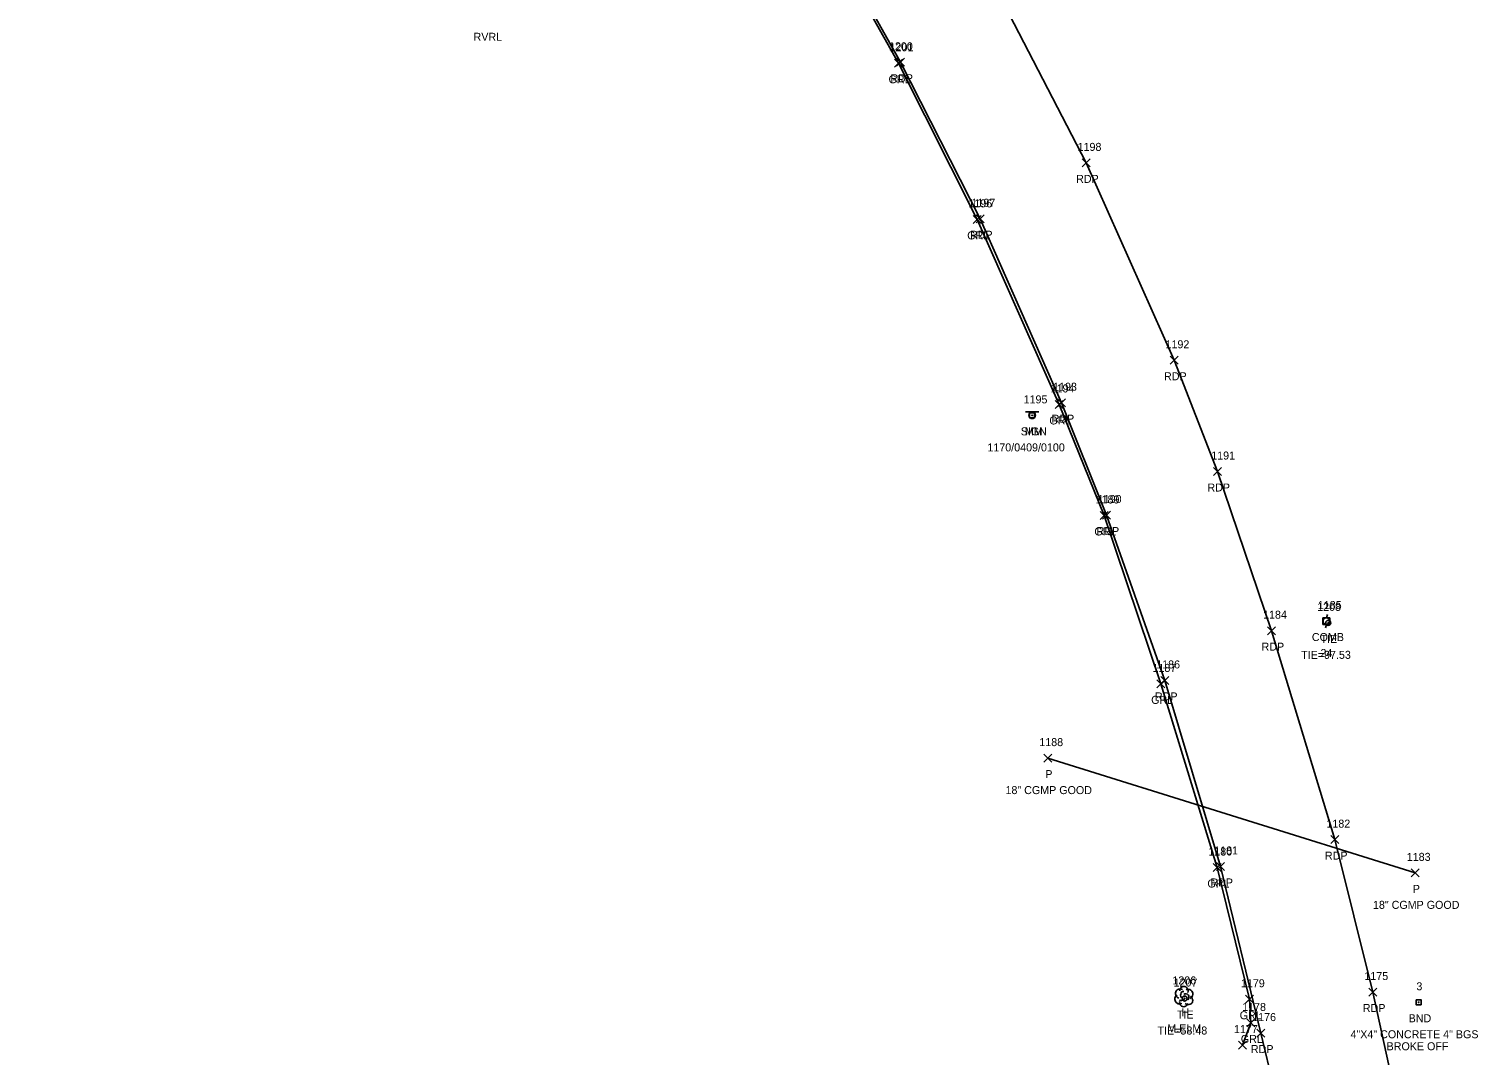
# Model space of a CAD drawing. Extents: x 1503463 to 1505240, y 712171 to 717196.
# Drawn here: x 1504313.5 to 1504675.6, y 714597.7 to 714854.3 of the extents above; entities that cross this region are included whole.
import ezdxf

# ---------------------------------------------------------------- set-up
doc = ezdxf.new("R2010")
doc.units = 0
for name, color, linetype in [('C_A', 7, 'Continuous'), ('C_C', 7, 'Continuous'), ('C_I', 7, 'Continuous'), ('CBP', 7, 'Continuous'), ('D_A', 7, 'Continuous'), ('D_C', 7, 'Continuous'), ('D_I', 7, 'Continuous'), ('D_TIC', 7, 'Continuous'), ('DCP', 7, 'Continuous'), ('L_A', 7, 'Continuous'), ('L_C', 7, 'Continuous'), ('L_I', 7, 'Continuous'), ('LTD', 7, 'Continuous'), ('M_A', 7, 'Continuous'), ('M_C', 7, 'Continuous'), ('M_I', 7, 'Continuous'), ('MHBP', 7, 'Continuous'), ('P_A', 7, 'Continuous'), ('P_I', 7, 'Continuous'), ('P_TIC', 7, 'Continuous'), ('PET', 7, 'Continuous'), ('R_A', 7, 'Continuous'), ('R_I', 7, 'Continuous'), ('R_TIC', 7, 'Continuous'), ('RGR', 7, 'Continuous'), ('S_A', 7, 'Continuous'), ('S_C', 7, 'Continuous'), ('S_I', 7, 'Continuous'), ('SRM', 7, 'Continuous'), ('SSGN', 7, 'Continuous'), ('U_A', 7, 'Continuous'), ('U_C', 7, 'Continuous'), ('U_I', 7, 'Continuous'), ('UP', 7, 'Continuous')]:
    doc.layers.add(name, color=color, linetype=linetype)

msp = doc.modelspace()

# ---------------------------------------------------------------- linework, layer by layer
at = {"layer": 'CBP'}
for centre, radius in [((1504638.16, 714705.79), 0.625), ((1504638.16, 714705.79), 0.0833), ((1504602.27, 714611.86), 0.625), ((1504602.27, 714611.86), 0.0833)]:
    msp.add_circle(centre, radius, dxfattribs=at)
at = {"layer": 'D_TIC'}
for points in [[(1504567.08, 714670.97), (1504569.08, 714672.97)], [(1504569.08, 714670.97), (1504567.08, 714672.97)], [(1504658.9, 714642.28), (1504660.9, 714644.28)], [(1504660.9, 714642.28), (1504658.9, 714644.28)]]:
    msp.add_lwpolyline(points, dxfattribs=at)
at = {"layer": 'DCP'}
msp.add_lwpolyline([(1504659.9, 714643.28), (1504568.08, 714671.97)], dxfattribs=at)
at = {"layer": 'LTD'}
msp.add_line((1504602.03, 714612.39), (1504602.03, 714612.39), dxfattribs=at)
msp.add_line((1504602.03, 714612.39), (1504602.03, 714612.39), dxfattribs=at)
msp.add_arc((1504602.08, 714613.82), 1.05, 335.5272, 180.9563, dxfattribs=at)
for centre, major_axis, ratio, start_param, end_param in [((1504600.95, 714611.68), (0.58, -1.04), 0.959034, 3.141593, 6.283185), ((1504601.24, 714613.05), (1.21, -0.51), 0.895232, 1.570796, 4.712389), ((1504602.03, 714610.89), (0.26, 1.06), 0.942809, 1.570796, 4.712389), ((1504601.57, 714611.64), (-0.625, -0.083), 0.423636, 0, 3.141593), ((1504601.82, 714612.84), (-0.208, -0.792), 0.645439, 3.141593, 6.283185), ((1504602.53, 714612.22), (-0.5, 0.667), 0.989748, 3.141593, 6.283185), ((1504603.03, 714611.55), (-1.09, 0.79), 0.841452, 1.570796, 4.712389), ((1504603.07, 714612.97), (-1.14, -0.48), 0.949671, 1.570796, 4.712389)]:
    msp.add_ellipse(centre, major_axis=major_axis, ratio=ratio, start_param=start_param, end_param=end_param, dxfattribs=at)
at = {"layer": 'MHBP'}
msp.add_lwpolyline([(1504660.12, 714611.54), (1504661.37, 714611.54), (1504661.37, 714610.29), (1504660.12, 714610.29)], close=True, dxfattribs=at)
msp.add_circle((1504660.75, 714610.92), 0.0833, dxfattribs=at)
at = {"layer": 'P_TIC'}
for points in [[(1504530.24, 714844.96), (1504532.24, 714846.96)], [(1504532.24, 714844.96), (1504530.24, 714846.96)], [(1504576.65, 714819.8), (1504578.65, 714821.8)], [(1504578.65, 714819.8), (1504576.65, 714821.8)], [(1504550.13, 714805.83), (1504552.13, 714807.83)], [(1504552.13, 714805.83), (1504550.13, 714807.83)], [(1504598.62, 714770.44), (1504600.62, 714772.44)], [(1504600.62, 714770.44), (1504598.62, 714772.44)], [(1504570.53, 714759.83), (1504572.53, 714761.83)], [(1504572.53, 714759.83), (1504570.53, 714761.83)], [(1504609.47, 714742.63), (1504611.47, 714744.63)], [(1504611.47, 714742.63), (1504609.47, 714744.63)], [(1504581.78, 714731.74), (1504583.78, 714733.74)], [(1504583.78, 714731.74), (1504581.78, 714733.74)], [(1504623, 714702.83), (1504625, 714704.83)], [(1504625, 714702.83), (1504623, 714704.83)], [(1504596.35, 714690.39), (1504598.35, 714692.39)], [(1504598.35, 714690.39), (1504596.35, 714692.39)], [(1504638.83, 714650.58), (1504640.83, 714652.58)], [(1504640.83, 714650.58), (1504638.83, 714652.58)], [(1504610.21, 714643.87), (1504612.21, 714645.87)], [(1504612.21, 714643.87), (1504610.21, 714645.87)], [(1504648.31, 714612.48), (1504650.31, 714614.48)], [(1504650.31, 714612.48), (1504648.31, 714614.48)], [(1504620.33, 714602.22), (1504622.33, 714604.22)], [(1504622.33, 714602.22), (1504620.33, 714604.22)]]:
    msp.add_lwpolyline(points, dxfattribs=at)
at = {"layer": 'PET'}
for points in [[(1504628.86, 714571.69), (1504621.33, 714603.22), (1504611.21, 714644.87), (1504597.35, 714691.39), (1504582.78, 714732.74), (1504571.53, 714760.83), (1504551.13, 714806.83), (1504531.24, 714845.96), (1504513.33, 714878.02), (1504484.92, 714923.88), (1504464.76, 714952.16), (1504434.64, 714992.6), (1504400.79, 715031.63), (1504363.93, 715069.91), (1504326.41, 715104.24), (1504288.97, 715135.69), (1504248.31, 715166.3), (1504201.61, 715200.45), (1504154.53, 715234.59), (1504120.68, 715258.8), (1504069.42, 715296.54), (1504012.71, 715338.31), (1504010.26, 715341.79), (1503951.37, 715387.03)], [(1504657.14, 714577.6), (1504649.31, 714613.48), (1504639.83, 714651.58), (1504624, 714703.83), (1504610.47, 714743.63), (1504599.62, 714771.44), (1504577.65, 714820.8), (1504557.24, 714860.24), (1504539.4, 714891.39), (1504508.82, 714940.05), (1504488.73, 714969.22), (1504457.88, 715009.77), (1504422.56, 715051.33), (1504384.13, 715091.33), (1504346.68, 715126.54), (1504308.22, 715158.84), (1504264.39, 715191.56), (1504218.27, 715225.33), (1504171.61, 715259.82), (1504137.77, 715284.36), (1504086.6, 715320.97), (1504048.23, 715348.08)]]:
    msp.add_lwpolyline(points, dxfattribs=at)
at = {"layer": 'R_TIC'}
for points in [[(1504529.74, 714844.7), (1504531.74, 714846.7)], [(1504531.74, 714844.7), (1504529.74, 714846.7)], [(1504549.39, 714805.66), (1504551.39, 714807.66)], [(1504551.39, 714805.66), (1504549.39, 714807.66)], [(1504569.9, 714759.4), (1504571.9, 714761.4)], [(1504571.9, 714759.4), (1504569.9, 714761.4)], [(1504581.15, 714731.64), (1504583.15, 714733.64)], [(1504583.15, 714731.64), (1504581.15, 714733.64)], [(1504595.35, 714689.53), (1504597.35, 714691.53)], [(1504597.35, 714689.53), (1504595.35, 714691.53)], [(1504609.41, 714643.61), (1504611.41, 714645.61)], [(1504611.41, 714643.61), (1504609.41, 714645.61)], [(1504617.48, 714610.67), (1504619.48, 714612.67)], [(1504619.48, 714610.67), (1504617.48, 714612.67)], [(1504617.77, 714604.75), (1504619.77, 714606.75)], [(1504619.77, 714604.75), (1504617.77, 714606.75)], [(1504615.71, 714599.2), (1504617.71, 714601.2)], [(1504617.71, 714599.2), (1504615.71, 714601.2)]]:
    msp.add_lwpolyline(points, dxfattribs=at)
at = {"layer": 'RGR'}
msp.add_lwpolyline([(1504616.71, 714600.2), (1504618.77, 714605.75), (1504618.48, 714611.67), (1504610.41, 714644.61), (1504596.35, 714690.53), (1504582.15, 714732.64), (1504570.9, 714760.4), (1504550.39, 714806.66), (1504530.74, 714845.7), (1504512.79, 714877.73), (1504484.33, 714923.22), (1504464.3, 714951.66), (1504433.51, 714991.73), (1504399.75, 715031.08), (1504363.28, 715069.4), (1504326.1, 715103.99), (1504288.79, 715135.46), (1504248.14, 715165.9), (1504201.6, 715200.12), (1504153.7, 715233.3), (1504118.14, 715255.35), (1504061.18, 715288.67)], dxfattribs=at)
at = {"layer": 'SRM'}
msp.add_lwpolyline([(1504563.52, 714758.29), (1504564.77, 714758.29), (1504564.77, 714757.04), (1504563.52, 714757.04)], close=True, dxfattribs=at)
msp.add_circle((1504564.15, 714757.66), 0.0833, dxfattribs=at)
at = {"layer": 'SSGN'}
for p, q in [((1504562.52, 714758.52), (1504565.85, 714758.52)), ((1504564.17, 714757.69), (1504564.17, 714757.69))]:
    msp.add_line(p, q, dxfattribs=at)
msp.add_circle((1504564.17, 714757.69), 0.833, dxfattribs=at)
at = {"layer": 'UP'}
for p, q in [((1504636.84, 714705.41), (1504636.84, 714707.08)), ((1504636.84, 714707.08), (1504638.51, 714707.08)), ((1504638.51, 714705.41), (1504636.84, 714705.41)), ((1504637.43, 714704.58), (1504637.68, 714705.41)), ((1504637.93, 714707.91), (1504637.68, 714707.08)), ((1504637.68, 714706.24), (1504637.68, 714706.24)), ((1504638.51, 714707.08), (1504638.51, 714705.41))]:
    msp.add_line(p, q, dxfattribs=at)
msp.add_circle((1504637.68, 714706.24), 0.833, dxfattribs=at)

# ---------------------------------------------------------------- texts
at = {"layer": 'C_A'}
for p in [(1504636.24, 714700.79), (1504600.35, 714606.86)]:
    msp.add_text('TIE', height=2, dxfattribs=at).set_placement(p)
at = {"layer": 'C_C'}
for s, p in [('TIE=97.53', (1504631.39, 714696.79)), ('TIE=58.48', (1504595.5, 714602.86))]:
    msp.add_text(s, height=2, dxfattribs=at).set_placement(p)
at = {"layer": 'C_I'}
for s, p in [('1208', (1504635.39, 714708.79)), ('1207', (1504599.5, 714614.86))]:
    msp.add_text(s, height=2, dxfattribs=at).set_placement(p)
at = {"layer": 'D_A'}
for p in [(1504567.45, 714666.97), (1504659.28, 714638.28)]:
    msp.add_text('P', height=2, dxfattribs=at).set_placement(p)
at = {"layer": 'D_C'}
for p in [(1504557.5, 714662.97), (1504649.33, 714634.28)]:
    msp.add_text('18" CGMP GOOD', height=2, dxfattribs=at).set_placement(p)
at = {"layer": 'D_I'}
for s, p in [('1188', (1504565.95, 714674.97)), ('1183', (1504657.78, 714646.28))]:
    msp.add_text(s, height=2, dxfattribs=at).set_placement(p)
at = {"layer": 'L_A'}
for s, p in [('RVRL', (1504424.57, 714851.32)), ('H', (1504601.46, 714607.39))]:
    msp.add_text(s, height=2, dxfattribs=at).set_placement(p)
at = {"layer": 'L_C'}
msp.add_text('M.ELM', height=2, dxfattribs=at).set_placement((1504597.94, 714603.39))
at = {"layer": 'L_I'}
msp.add_text('1206', height=2, dxfattribs=at).set_placement((1504599.2, 714615.39))
at = {"layer": 'M_A'}
msp.add_text('BND', height=2, dxfattribs=at).set_placement((1504658.24, 714605.92))
at = {"layer": 'M_C'}
for s, p in [('4"X4" CONCRETE 4" BGS', (1504643.72, 714601.92)), ('BROKE OFF', (1504652.74, 714598.92))]:
    msp.add_text(s, height=2, dxfattribs=at).set_placement(p)
at = {"layer": 'M_I'}
msp.add_text('3', height=2, dxfattribs=at).set_placement((1504660.18, 714613.92))
at = {"layer": 'P_A'}
for p in [(1504528.73, 714840.96), (1504575.14, 714815.8), (1504548.62, 714801.83), (1504597.11, 714766.44), (1504569.02, 714755.83), (1504607.95, 714738.63), (1504580.26, 714727.74), (1504621.49, 714698.83), (1504594.84, 714686.39), (1504637.32, 714646.58), (1504608.7, 714639.87), (1504646.8, 714608.48), (1504618.82, 714598.22)]:
    msp.add_text('RDP', height=2, dxfattribs=at).set_placement(p)
at = {"layer": 'P_I'}
for s, p in [('1200', (1504528.38, 714848.96)), ('1198', (1504575.52, 714823.8)), ('1197', (1504549, 714809.83)), ('1192', (1504597.49, 714774.44)), ('1193', (1504569.4, 714763.83)), ('1191', (1504608.91, 714746.63)), ('1190', (1504580.56, 714735.74)), ('1184', (1504621.87, 714706.83)), ('1186', (1504595.17, 714694.39)), ('1182', (1504637.7, 714654.58)), ('1181', (1504609.65, 714647.87)), ('1175', (1504647.18, 714616.48)), ('1176', (1504619.15, 714606.22))]:
    msp.add_text(s, height=2, dxfattribs=at).set_placement(p)
at = {"layer": 'R_A'}
for p in [(1504528.28, 714840.7), (1504547.93, 714801.66), (1504568.45, 714755.4), (1504579.7, 714727.64), (1504593.9, 714685.53), (1504607.95, 714639.61), (1504616.02, 714606.67), (1504616.31, 714600.75)]:
    msp.add_text('GRL', height=2, dxfattribs=at).set_placement(p)
at = {"layer": 'R_I'}
for s, p in [('1201', (1504528.53, 714848.7)), ('1196', (1504548.21, 714809.66)), ('1194', (1504568.78, 714763.4)), ('1189', (1504580.02, 714735.64)), ('1187', (1504594.23, 714693.53)), ('1180', (1504608.2, 714647.61)), ('1179', (1504616.34, 714614.67)), ('1178', (1504616.64, 714608.75)), ('1177', (1504614.58, 714603.2))]:
    msp.add_text(s, height=2, dxfattribs=at).set_placement(p)
at = {"layer": 'S_A'}
for s, p in [('SIGN', (1504561.31, 714752.66)), ('MM', (1504562.34, 714752.66))]:
    msp.add_text(s, height=2, dxfattribs=at).set_placement(p)
at = {"layer": 'S_C'}
msp.add_text('1170/0409/0100', height=2, dxfattribs=at).set_placement((1504552.98, 714748.66))
at = {"layer": 'S_I'}
msp.add_text('1195', height=2, dxfattribs=at).set_placement((1504562.02, 714760.66))
msp.add_text('1195', height=2, dxfattribs=at).set_placement((1504562.02, 714760.66))
at = {"layer": 'U_A'}
msp.add_text('COMB', height=2, dxfattribs=at).set_placement((1504634.06, 714701.24))
at = {"layer": 'U_C'}
msp.add_text('24', height=2, dxfattribs=at).set_placement((1504636.21, 714697.24))
at = {"layer": 'U_I'}
msp.add_text('1185', height=2, dxfattribs=at).set_placement((1504635.55, 714709.24))

doc.saveas('drawing.dxf')
